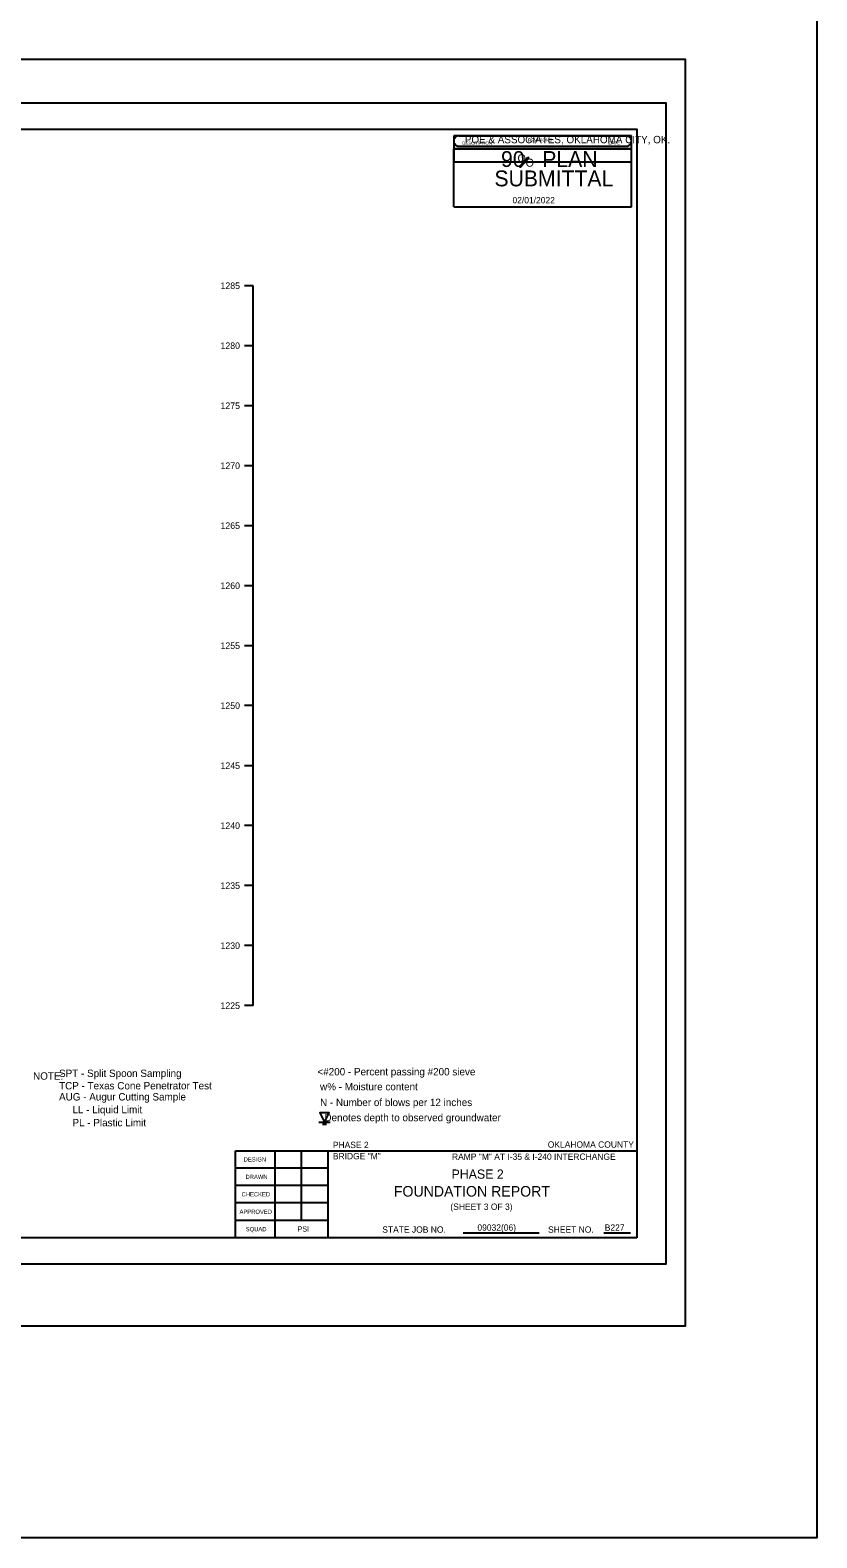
# Model space of a CAD drawing. Extents: x 2150161.5 to 2150203.1, y 143779.5 to 143868.5.
# Drawn here: x 2150188.17 to 2150203.07, y 143779.54 to 143808.09 of the extents above; entities that cross this region are included whole.
import ezdxf

# ---------------------------------------------------------------- set-up
doc = ezdxf.new("R2010")
doc.units = 0
for name, color, linetype in [('Default', 7, 'Continuous'), ('S', 7, 'Continuous'), ('SHT_Plot_Shape_Full', 7, 'Continuous'), ('SHT_Plot_Shape_Half', 7, 'Continuous'), ('SHT_Sheet_Border', 7, 'Continuous'), ('SHT_Stamp_90_Submit', 7, 'Continuous'), ('SHT_Stamp_Rev_Block', 7, 'Continuous'), ('SHT_Standard_Sheet_Lines', 7, 'Continuous'), ('SHT_Standard_Sheet_Txt', 7, 'Continuous'), ('T', 7, 'Continuous'), ('T-Title', 7, 'Continuous'), ('Text', 7, 'Continuous')]:
    doc.layers.add(name, color=color, linetype=linetype)

# ---------------------------------------------------------------- blocks, each defined once
blk = doc.blocks.new('DGRFC_WTLEV1')
at = {"layer": 'Default'}
for points in [[(-0.0127, 0), (0.0127, 0)], [(0, 0), (0.0106, 0.0212), (-0.0106, 0.0212), (0, 0)], [(-0.0042, -0.0042), (0.0042, -0.0042)]]:
    blk.add_lwpolyline(points, dxfattribs=at)

msp = doc.modelspace()

# ---------------------------------------------------------------- linework, layer by layer
at = {"layer": 'Default'}
msp.add_line((2150192.396, 143789.617), (2150192.396, 143803.253), dxfattribs=at)
for points in [[(2150192.396, 143803.253), (2150192.229, 143803.253)], [(2150192.396, 143802.117), (2150192.229, 143802.117)], [(2150192.396, 143800.98), (2150192.229, 143800.98)], [(2150192.396, 143799.844), (2150192.229, 143799.844)], [(2150192.396, 143798.708), (2150192.229, 143798.708)], [(2150192.396, 143797.571), (2150192.229, 143797.571)], [(2150192.396, 143796.435), (2150192.229, 143796.435)], [(2150192.396, 143795.299), (2150192.229, 143795.299)], [(2150192.396, 143794.162), (2150192.229, 143794.162)], [(2150192.396, 143793.026), (2150192.229, 143793.026)], [(2150192.396, 143791.89), (2150192.229, 143791.89)], [(2150192.396, 143790.753), (2150192.229, 143790.753)], [(2150192.396, 143789.617), (2150192.229, 143789.617)]]:
    msp.add_lwpolyline(points, dxfattribs=at)
at = {"layer": 'S'}
msp.add_lwpolyline([(2150161.53, 143868.477), (2150203.071, 143868.477), (2150203.071, 143779.536), (2150161.53, 143779.536)], close=True, dxfattribs=at)
at = {"layer": 'SHT_Plot_Shape_Full'}
msp.add_lwpolyline([(2150164.575, 143807.544), (2150200.575, 143807.544), (2150200.575, 143783.544), (2150164.575, 143783.544)], close=True, dxfattribs=at)
at = {"layer": 'SHT_Plot_Shape_Half'}
msp.add_lwpolyline([(2150166.212, 143806.719), (2150200.212, 143806.719), (2150200.212, 143784.719), (2150166.212, 143784.719)], close=True, dxfattribs=at)
at = {"layer": 'SHT_Sheet_Border'}
for p, q in [((2150192.062, 143785.219), (2150192.062, 143786.869)), ((2150192.062, 143786.869), (2150199.662, 143786.869)), ((2150193.812, 143785.219), (2150193.812, 143786.87))]:
    msp.add_line(p, q, dxfattribs=at)
msp.add_lwpolyline([(2150199.662, 143785.219), (2150168.162, 143785.219), (2150168.162, 143806.219), (2150199.662, 143806.219)], close=True, dxfattribs=at)
at = {"layer": 'SHT_Stamp_90_Submit'}
for p, q in [((2150196.293, 143806.095), (2150199.459, 143806.095)), ((2150196.193, 143805.845), (2150199.559, 143805.845)), ((2150196.193, 143804.746), (2150196.193, 143805.845)), ((2150196.293, 143805.895), (2150199.459, 143805.895)), ((2150199.559, 143804.746), (2150199.559, 143805.845)), ((2150197.437, 143805.506), (2150197.592, 143805.679)), ((2150197.437, 143805.506), (2150197.467, 143805.506)), ((2150197.454, 143805.506), (2150197.61, 143805.679)), ((2150197.459, 143805.506), (2150197.615, 143805.679)), ((2150197.467, 143805.506), (2150197.623, 143805.679)), ((2150197.592, 143805.679), (2150197.623, 143805.679)), ((2150196.193, 143804.746), (2150199.559, 143804.746))]:
    msp.add_line(p, q, dxfattribs=at)
for centre, start, end in [((2150196.294, 143805.995), 89.9952, 270), ((2150199.46, 143805.995), 270, 90.0048)]:
    msp.add_arc(centre, 0.1, start, end, dxfattribs=at)
at = {"layer": 'SHT_Stamp_Rev_Block'}
for p, q in [((2150196.194, 143806.095), (2150196.194, 143805.595)), ((2150199.559, 143806.095), (2150196.194, 143806.095)), ((2150199.559, 143805.595), (2150199.559, 143806.095)), ((2150199.559, 143805.845), (2150196.194, 143805.845)), ((2150199.559, 143805.595), (2150196.194, 143805.595))]:
    msp.add_line(p, q, dxfattribs=at)
at = {"layer": 'SHT_Standard_Sheet_Lines'}
for p, q in [((2150192.812, 143785.219), (2150192.812, 143786.87)), ((2150193.312, 143785.549), (2150193.312, 143786.87)), ((2150196.373, 143785.315), (2150197.813, 143785.315)), ((2150199.038, 143785.315), (2150199.54, 143785.315))]:
    msp.add_line(p, q, dxfattribs=at)
for points in [[(2150193.812, 143786.539), (2150192.062, 143786.539)], [(2150193.812, 143786.209), (2150192.062, 143786.209)], [(2150193.812, 143785.879), (2150192.062, 143785.879)], [(2150193.812, 143785.549), (2150192.062, 143785.549)]]:
    msp.add_lwpolyline(points, dxfattribs=at)

# ---------------------------------------------------------------- block references
at = {"layer": 'Default', "xscale": 8.503919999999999, "yscale": 8.503919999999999}
msp.add_blockref('DGRFC_WTLEV1', (2150193.745, 143787.409), dxfattribs=at)

# ---------------------------------------------------------------- texts
at = {"layer": 'Default'}
for s, p in [('1285', (2150191.776, 143803.191)), ('1280', (2150191.776, 143802.055)), ('1275', (2150191.776, 143800.918)), ('1270', (2150191.776, 143799.782)), ('1265', (2150191.776, 143798.646)), ('1260', (2150191.776, 143797.509)), ('1255', (2150191.776, 143796.373)), ('1250', (2150191.776, 143795.237)), ('1245', (2150191.776, 143794.1)), ('1240', (2150191.776, 143792.964)), ('1235', (2150191.776, 143791.828)), ('1230', (2150191.776, 143790.691)), ('1225', (2150191.776, 143789.555))]:
    msp.add_text(s, height=0.124, dxfattribs=at).set_placement(p)
at = {"layer": 'Defpoints'}
msp.add_text('PHASE 2', height=0.175, dxfattribs=at).set_placement((2150196.152, 143786.338))
at = {"layer": 'SHT_Stamp_90_Submit'}
for s, height, p in [('POE & ASSOCIATES, OKLAHOMA CITY, OK.', 0.14, (2150196.403, 143805.952)), ('90   PLAN', 0.3, (2150197.089, 143805.503)), ('O', 0.153, (2150197.402, 143805.591)), ('O', 0.153, (2150197.554, 143805.507)), ('SUBMITTAL', 0.3, (2150196.964, 143805.136)), ('02/01/2022', 0.12, (2150197.306, 143804.814))]:
    msp.add_text(s, height=height, dxfattribs=at).set_placement(p)
at = {"layer": 'SHT_Stamp_Rev_Block'}
for s, height, p in [('DESCRIPTION', 0.05999, (2150196.353, 143805.923)), ('REVISIONS', 0.06, (2150197.602, 143805.982)), ('DATE', 0.06, (2150199.123, 143805.927))]:
    msp.add_text(s, height=height, dxfattribs=at).set_placement(p)
at = {"layer": 'SHT_Standard_Sheet_Txt'}
for s, height, p in [('DESIGN', 0.08, (2150192.215, 143786.664)), ('DRAWN', 0.08, (2150192.25, 143786.334)), ('CHECKED', 0.08, (2150192.175, 143786.004)), ('APPROVED', 0.08, (2150192.136, 143785.673)), ('SQUAD', 0.08, (2150192.254, 143785.343)), ('STATE JOB NO.', 0.12, (2150194.84, 143785.315)), ('SHEET NO. ', 0.12, (2150197.98, 143785.315))]:
    msp.add_text(s, height=height, dxfattribs=at).set_placement(p)
at = {"layer": 'T'}
for s, height, p in [('PHASE 2', 0.12, (2150193.904, 143786.918)), ('OKLAHOMA COUNTY', 0.12, (2150197.974, 143786.926)), ('BRIDGE "M"', 0.12, (2150193.904, 143786.706)), ('RAMP "M" AT I-35 & I-240 INTERCHANGE', 0.12, (2150196.16, 143786.696)), ('(SHEET 3 OF 3)', 0.12, (2150196.13, 143785.748)), ('PSI', 0.1, (2150193.232, 143785.337)), ('09032(06)', 0.12, (2150196.642, 143785.353)), ('B227', 0.12, (2150199.054, 143785.353))]:
    msp.add_text(s, height=height, dxfattribs=at).set_placement(p)
at = {"layer": 'T-Title'}
msp.add_text('FOUNDATION REPORT', height=0.2, dxfattribs=at).set_placement((2150195.059, 143786))
at = {"layer": 'Text'}
for s, p in [('    SPT - Split Spoon Sampling', (2150188.51, 143788.265)), (' <#200 - Percent passing #200 sieve', (2150193.56, 143788.295)), ('NOTE:', (2150188.226, 143788.214)), ('    TCP - Texas Cone Penetrator Test', (2150188.51, 143788.03)), ('w% - Moisture content', (2150193.661, 143788.013)), ('    AUG - Augur Cutting Sample', (2150188.51, 143787.82)), ('N - Number of blows per 12 inches', (2150193.661, 143787.714)), (' LL - Liquid Limit', (2150188.92, 143787.578)), ('    Denotes depth to observed groundwater', (2150193.536, 143787.427)), (' PL - Plastic Limit', (2150188.92, 143787.331))]:
    msp.add_text(s, height=0.14, dxfattribs=at).set_placement(p)

doc.saveas('drawing.dxf')
